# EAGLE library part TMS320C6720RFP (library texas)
Floating-Point Digital Signal Processors Source: http://focus.ti.com/lit/ds/symlink/tms320c6720.pdf
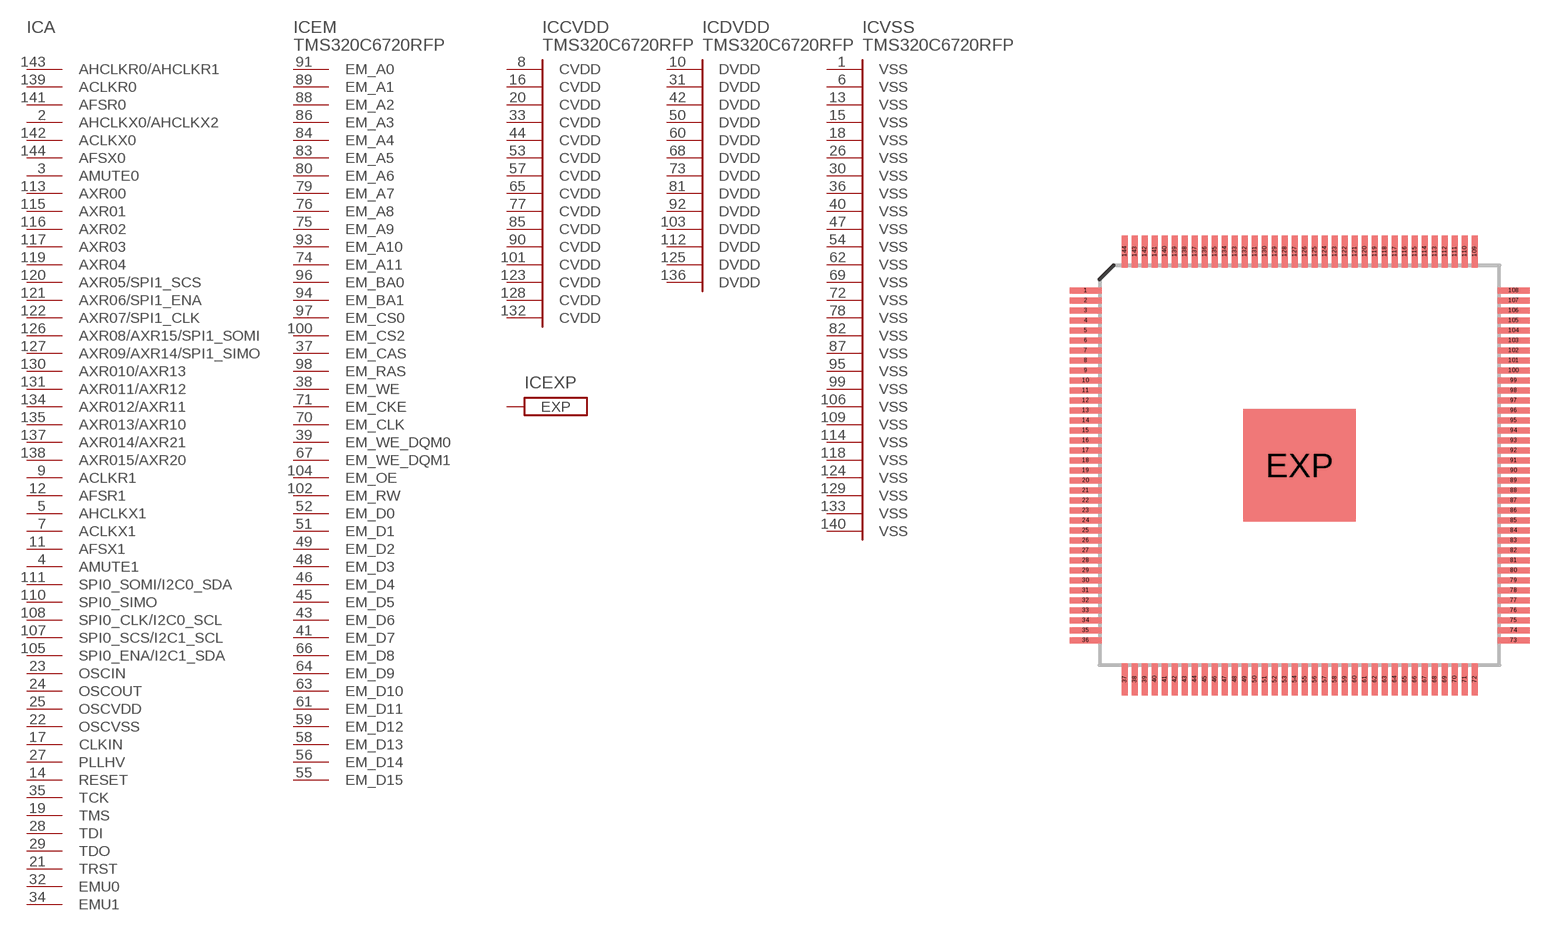
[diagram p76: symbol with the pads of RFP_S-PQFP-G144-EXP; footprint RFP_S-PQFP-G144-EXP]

Designator prefix IC; gates A=TMS320C6720-QFP-A EM=TMS320C6720-QFP-EM CVDD=TMS320C6720-QFP-CVDD DVDD=TMS320C6720-QFP-DVDD VSS=TMS320C6720-QFP-VSS EXP=EXP1

## TMS320C6720RFP (MPN: TMS320C6720BRFP200; OC_FARNELL: 1555284; OC_NEWARK: 30M1816)  [RFP_S-PQFP-G144-EXP]
1  VSS:VSS  pwr
2  A:AHCLKX0/AHCLKX2
3  A:AMUTE0  out
4  A:AMUTE1  out
5  A:AHCLKX1
6  VSS:VSS  pwr
7  A:ACLKX1
8  CVDD:CVDD  pwr
9  A:ACLKR1
10  DVDD:DVDD  pwr
11  A:AFSX1
12  A:AFSR1
13  VSS:VSS  pwr
14  A:RESET  in
15  VSS:VSS  pwr
16  CVDD:CVDD  pwr
17  A:CLKIN  in
18  VSS:VSS  pwr
19  A:TMS  in
20  CVDD:CVDD  pwr
21  A:TRST  in
22  A:OSCVSS  pwr
23  A:OSCIN  in
24  A:OSCOUT  out
25  A:OSCVDD  pwr
26  VSS:VSS  pwr
27  A:PLLHV  pwr
28  A:TDI  in
29  A:TDO  hiz
30  VSS:VSS  pwr
31  DVDD:DVDD  pwr
32  A:EMU0
33  CVDD:CVDD  pwr
34  A:EMU1
35  A:TCK  in
36  VSS:VSS  pwr
37  EM:EM_CAS  out
38  EM:EM_WE  out
39  EM:EM_WE_DQM0  out
40  VSS:VSS  pwr
41  EM:EM_D7
42  DVDD:DVDD  pwr
43  EM:EM_D6
44  CVDD:CVDD  pwr
45  EM:EM_D5
46  EM:EM_D4
47  VSS:VSS  pwr
48  EM:EM_D3
49  EM:EM_D2
50  DVDD:DVDD  pwr
51  EM:EM_D1
52  EM:EM_D0
53  CVDD:CVDD  pwr
54  VSS:VSS  pwr
55  EM:EM_D15
56  EM:EM_D14
57  CVDD:CVDD  pwr
58  EM:EM_D13
59  EM:EM_D12
60  DVDD:DVDD  pwr
61  EM:EM_D11
62  VSS:VSS  pwr
63  EM:EM_D10
64  EM:EM_D9
65  CVDD:CVDD  pwr
66  EM:EM_D8
67  EM:EM_WE_DQM1  out
68  DVDD:DVDD  pwr
69  VSS:VSS  pwr
70  EM:EM_CLK  out
71  EM:EM_CKE  out
72  VSS:VSS  pwr
73  DVDD:DVDD  pwr
74  EM:EM_A11  out
75  EM:EM_A9  out
76  EM:EM_A8  out
77  CVDD:CVDD  pwr
78  VSS:VSS  pwr
79  EM:EM_A7  out
80  EM:EM_A6  out
81  DVDD:DVDD  pwr
82  VSS:VSS  pwr
83  EM:EM_A5  out
84  EM:EM_A4  out
85  CVDD:CVDD  pwr
86  EM:EM_A3  out
87  VSS:VSS  pwr
88  EM:EM_A2  out
89  EM:EM_A1  out
90  CVDD:CVDD  pwr
91  EM:EM_A0  out
92  DVDD:DVDD  pwr
93  EM:EM_A10  out
94  EM:EM_BA1  out
95  VSS:VSS  pwr
96  EM:EM_BA0  out
97  EM:EM_CS0  out
98  EM:EM_RAS  out
99  VSS:VSS  pwr
100  EM:EM_CS2  out
101  CVDD:CVDD  pwr
102  EM:EM_RW  out
103  DVDD:DVDD  pwr
104  EM:EM_OE  out
105  A:SPI0_ENA/I2C1_SDA
106  VSS:VSS  pwr
107  A:SPI0_SCS/I2C1_SCL
108  A:SPI0_CLK/I2C0_SCL
109  VSS:VSS  pwr
110  A:SPI0_SIMO
111  A:SPI0_SOMI/I2C0_SDA
112  DVDD:DVDD  pwr
113  A:AXR00
114  VSS:VSS  pwr
115  A:AXR01
116  A:AXR02
117  A:AXR03
118  VSS:VSS  pwr
119  A:AXR04
120  A:AXR05/SPI1_SCS
121  A:AXR06/SPI1_ENA
122  A:AXR07/SPI1_CLK
123  CVDD:CVDD  pwr
124  VSS:VSS  pwr
125  DVDD:DVDD  pwr
126  A:AXR08/AXR15/SPI1_SOMI
127  A:AXR09/AXR14/SPI1_SIMO
128  CVDD:CVDD  pwr
129  VSS:VSS  pwr
130  A:AXR010/AXR13
131  A:AXR011/AXR12
132  CVDD:CVDD  pwr
133  VSS:VSS  pwr
134  A:AXR012/AXR11
135  A:AXR013/AXR10
136  DVDD:DVDD  pwr
137  A:AXR014/AXR21
138  A:AXR015/AXR20
139  A:ACLKR0
140  VSS:VSS  pwr
141  A:AFSR0
142  A:ACLKX0
143  A:AHCLKR0/AHCLKR1
144  A:AFSX0
EXP  EXP:EXP  in

## Footprint RFP_S-PQFP-G144-EXP (pad centres in mm)
RFP (S-PQFP-G144) PowerPAD TM Source: http://focus.ti.com/lit/ds/symlink/tms320c6720.pdf
smd 1.6 x 0.3: 1 -10.7,8.75; 2 -10.7,8.25; 3 -10.7,7.75; 4 -10.7,7.25; 5 -10.7,6.75; 6 -10.7,6.25; 7 -10.7,5.75; 8 -10.7,5.25; 9 -10.7,4.75; 10 -10.7,4.25; 11 -10.7,3.75; 12 -10.7,3.25; 13 -10.7,2.75; 14 -10.7,2.25; 15 -10.7,1.75; 16 -10.7,1.25; 17 -10.7,0.75; 18 -10.7,0.25; 19 -10.7,-0.25; 20 -10.7,-0.75; 21 -10.7,-1.25; 22 -10.7,-1.75; 23 -10.7,-2.25; 24 -10.7,-2.75; 25 -10.7,-3.25; 26 -10.7,-3.75; 27 -10.7,-4.25; 28 -10.7,-4.75; 29 -10.7,-5.25; 30 -10.7,-5.75; 31 -10.7,-6.25; 32 -10.7,-6.75; 33 -10.7,-7.25; 34 -10.7,-7.75; 35 -10.7,-8.25; 36 -10.7,-8.75; 73 10.7,-8.75; 74 10.7,-8.25; 75 10.7,-7.75; 76 10.7,-7.25; 77 10.7,-6.75; 78 10.7,-6.25; 79 10.7,-5.75; 80 10.7,-5.25; 81 10.7,-4.75; 82 10.7,-4.25; 83 10.7,-3.75; 84 10.7,-3.25; 85 10.7,-2.75; 86 10.7,-2.25; 87 10.7,-1.75; 88 10.7,-1.25; 89 10.7,-0.75; 90 10.7,-0.25; 91 10.7,0.25; 92 10.7,0.75; 93 10.7,1.25; 94 10.7,1.75; 95 10.7,2.25; 96 10.7,2.75; 97 10.7,3.25; 98 10.7,3.75; 99 10.7,4.25; 100 10.7,4.75; 101 10.7,5.25; 102 10.7,5.75; 103 10.7,6.25; 104 10.7,6.75; 105 10.7,7.25; 106 10.7,7.75; 107 10.7,8.25; 108 10.7,8.75
smd 0.3 x 1.6: 37 -8.75,-10.7; 38 -8.25,-10.7; 39 -7.75,-10.7; 40 -7.25,-10.7; 41 -6.75,-10.7; 42 -6.25,-10.7; 43 -5.75,-10.7; 44 -5.25,-10.7; 45 -4.75,-10.7; 46 -4.25,-10.7; 47 -3.75,-10.7; 48 -3.25,-10.7; 49 -2.75,-10.7; 50 -2.25,-10.7; 51 -1.75,-10.7; 52 -1.25,-10.7; 53 -0.75,-10.7; 54 -0.25,-10.7; 55 0.25,-10.7; 56 0.75,-10.7; 57 1.25,-10.7; 58 1.75,-10.7; 59 2.25,-10.7; 60 2.75,-10.7; 61 3.25,-10.7; 62 3.75,-10.7; 63 4.25,-10.7; 64 4.75,-10.7; 65 5.25,-10.7; 66 5.75,-10.7; 67 6.25,-10.7; 68 6.75,-10.7; 69 7.25,-10.7; 70 7.75,-10.7; 71 8.25,-10.7; 72 8.75,-10.7; 109 8.75,10.7; 110 8.25,10.7; 111 7.75,10.7; 112 7.25,10.7; 113 6.75,10.7; 114 6.25,10.7; 115 5.75,10.7; 116 5.25,10.7; 117 4.75,10.7; 118 4.25,10.7; 119 3.75,10.7; 120 3.25,10.7; 121 2.75,10.7; 122 2.25,10.7; 123 1.75,10.7; 124 1.25,10.7; 125 0.75,10.7; 126 0.25,10.7; 127 -0.25,10.7; 128 -0.75,10.7; 129 -1.25,10.7; 130 -1.75,10.7; 131 -2.25,10.7; 132 -2.75,10.7; 133 -3.25,10.7; 134 -3.75,10.7; 135 -4.25,10.7; 136 -4.75,10.7; 137 -5.25,10.7; 138 -5.75,10.7; 139 -6.25,10.7; 140 -6.75,10.7; 141 -7.25,10.7; 142 -7.75,10.7; 143 -8.25,10.7; 144 -8.75,10.7
smd 5.61 x 5.61: EXP 0,0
